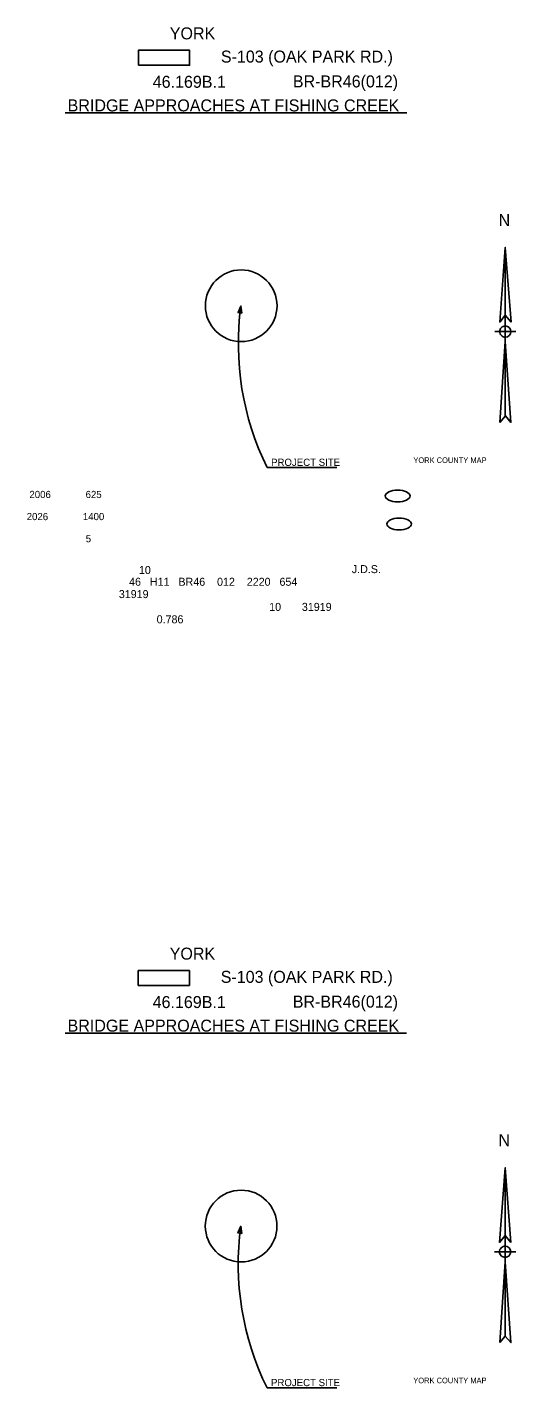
# Model space of a CAD drawing. Extents: x 12719 to 14316, y 14913 to 22622.
# Drawn here: x 13211 to 13822, y 20922 to 22622 of the extents above; entities that cross this region are included whole.
import ezdxf

# ---------------------------------------------------------------- set-up
doc = ezdxf.new("R2010")
doc.units = 0
doc.layers.add('Level 41', color=7, linetype='Continuous')

msp = doc.modelspace()

# ---------------------------------------------------------------- linework, layer by layer
at = {"layer": 'Level 41'}
for p, q in [((13259, 22515.4), (13685.9, 22515.4)), ((13809.2, 22347.2), (13802.3, 22253.9)), ((13809.2, 22347.2), (13816.5, 22253.9)), ((13809.2, 22347.2), (13809.2, 22136.5)), ((13809.2, 22262.4), (13802.3, 22253.9)), ((13809.2, 22262.4), (13816.5, 22253.9)), ((13796, 22242.1), (13822.4, 22242.1)), ((13809.2, 22229.5), (13802.3, 22128.6)), ((13809.2, 22229.5), (13816.3, 22128.6)), ((13802.3, 22128.6), (13809.3, 22136.7)), ((13816.3, 22128.6), (13809.3, 22136.7)), ((13598.7, 22072.2), (13511.4, 22072.2)), ((13258.9, 21365.4), (13685.8, 21365.4)), ((13809.1, 21197.2), (13802.1, 21103.9)), ((13809.1, 21197.2), (13816.3, 21103.9)), ((13809.1, 21197.2), (13809.1, 20986.5)), ((13809.1, 21112.4), (13802.1, 21103.9)), ((13809.1, 21112.4), (13816.3, 21103.9)), ((13795.8, 21092.1), (13822.2, 21092.1)), ((13809.1, 21079.5), (13802.2, 20978.6)), ((13809.1, 21079.5), (13816.2, 20978.6)), ((13802.2, 20978.6), (13809.1, 20986.7)), ((13816.2, 20978.6), (13809.1, 20986.7)), ((13598.6, 20922.2), (13511.3, 20922.2))]:
    msp.add_line(p, q, dxfattribs=at)
for points in [[(13350.4, 22574.9), (13414.4, 22574.9), (13414.4, 22593.6), (13350.4, 22593.6)], [(13479.7, 22265.1), (13478.6, 22274), (13475.1, 22265.7)], [(13350.3, 21424.9), (13414.3, 21424.9), (13414.3, 21443.6), (13350.3, 21443.6)], [(13479.6, 21115.1), (13478.4, 21124), (13475, 21115.7)]]:
    msp.add_lwpolyline(points, close=True, dxfattribs=at)
for points in [[(13809.2, 22262.4), (13809.2, 22347.2), (13802.3, 22253.9), (13809.2, 22262.4)], [(13802.2, 22242.1), (13809.2, 22242.1)], [(13809.2, 22242.1), (13809.2, 22249.1)], [(13809.2, 22242.1), (13809.2, 22235.1)], [(13816.2, 22242.1), (13809.2, 22242.1)], [(13809.2, 22229.5), (13809.2, 22136.6), (13809.3, 22136.7), (13816.3, 22128.6), (13809.2, 22229.5)], [(13809.1, 21112.4), (13809.1, 21197.2), (13802.1, 21103.9), (13809.1, 21112.4)], [(13802, 21092.1), (13809.1, 21092.1)], [(13809.1, 21092.1), (13809.1, 21099.1)], [(13809.1, 21092.1), (13809.1, 21085.1)], [(13816, 21092.1), (13809.1, 21092.1)], [(13809.1, 21079.5), (13809.1, 20986.6), (13809.1, 20986.7), (13816.2, 20978.6), (13809.1, 21079.5)]]:
    msp.add_lwpolyline(points, dxfattribs=at)
for centre in [(13479, 22274.3), (13478.9, 21124.3)]:
    msp.add_circle(centre, 44.8, dxfattribs=at)
for centre, radius, start, end in [((13827.8, 22227.2), 352.4, 172.3736, 206.1132), ((13809.2, 22242.1), 7, 89.5907, 180), ((13809.2, 22242.1), 7, 89.5907, 180), ((13809.2, 22242.1), 7, 180, 270.4093), ((13809.2, 22242.1), 7, 0, 89.5907), ((13809.2, 22242.1), 7, 270.4093, 0), ((13809.2, 22242.1), 7, 270.4093, 0), ((13827.7, 21077.2), 352.4, 172.3736, 206.1132), ((13809, 21092.1), 7, 89.5907, 180), ((13809, 21092.1), 7, 89.5907, 180), ((13809, 21092.1), 7, 180, 270.4093), ((13809, 21092.1), 7, 0, 89.5907), ((13809, 21092.1), 7, 270.4093, 0), ((13809, 21092.1), 7, 270.4093, 0)]:
    msp.add_arc(centre, radius, start, end, dxfattribs=at)
for centre in [(13674.7, 22036.6), (13676.5, 22001.6)]:
    msp.add_ellipse(centre, major_axis=(15.5, 0), ratio=0.468392, dxfattribs=at)

# ---------------------------------------------------------------- texts
for s, height, p in [('YORK', 15, (13389.7, 22607.2)), ('S-103 (OAK PARK RD.)', 15, (13453.6, 22578.2)), ('BR-BR46(012)', 15, (13543.6, 22547.2)), ('46.169B.1', 15, (13368.4, 22546.7)), ('BRIDGE APPROACHES AT FISHING CREEK', 15, (13262, 22517.2)), ('N', 15, (13800.8, 22374)), ('PROJECT SITE', 9, (13516.4, 22074.2)), ('YORK COUNTY MAP', 7, (13694.3, 22077.8)), ('2006             625', 9, (13214.2, 22034)), ('2026             1400', 9, (13210.8, 22006.4)), ('                 5', 9, (13227.8, 21978.8)), ('J.D.S.', 10, (13617.3, 21940.2)), ('46   H11   BR46    012    2220   654', 10, (13338.8, 21924.4)), ('10', 10, (13351.1, 21939.1)), ('31919', 10, (13326, 21909)), ('10       31919', 10, (13514, 21893)), ('0.786', 10, (13373.3, 21877.5)), ('YORK', 15, (13389.6, 21457.2)), ('S-103 (OAK PARK RD.)', 15, (13453.4, 21428.2)), ('46.169B.1', 15, (13368.3, 21396.7)), ('BR-BR46(012)', 15, (13543.5, 21397.2)), ('BRIDGE APPROACHES AT FISHING CREEK', 15, (13261.9, 21367.2)), ('N', 15, (13800.7, 21224)), ('PROJECT SITE', 9, (13516.3, 20924.2)), ('YORK COUNTY MAP', 7, (13694.2, 20927.8))]:
    msp.add_text(s, height=height, dxfattribs=at).set_placement(p)

doc.saveas('drawing.dxf')
